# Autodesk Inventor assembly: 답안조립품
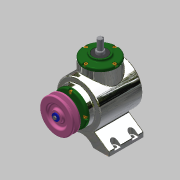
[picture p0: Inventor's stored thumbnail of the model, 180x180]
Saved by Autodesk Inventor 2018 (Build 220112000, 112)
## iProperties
Created: 2021-04
Part Number: 답안조립품
Material: 일반
Document SubType Name: Assembly
Designer: home
Author: home
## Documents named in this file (17)
- C:\Users\home\Desktop\710407V1014\답안조립품.iam
- C:\Users\home\Desktop\710407V1014\본체.ipt
- C:\Users\home\Desktop\710407V1014\커버.ipt
- C:\Users\home\Desktop\710407V1014\베어링 6203.ipt
- C:\Users\home\Desktop\710407V1014\오일실 17 x 32 x 8.ipt
- C:\Users\home\Desktop\710407V1014\메인 축.ipt
- 메인 축.ipt
- C:\Users\home\Desktop\710407V1014\키 5 x 5 x 14.ipt
- C:\Users\home\Desktop\710407V1014\메인 베벨기어.ipt
- C:\Users\home\Desktop\710407V1014\서브 축.ipt
- 서브 축.ipt
- C:\Users\home\Desktop\710407V1014\키 4 x 4 x 14.ipt
- C:\Users\home\Desktop\710407V1014\서브 베벨기어.ipt
- C:\Users\home\Desktop\710407V1014\V-벨트풀리.ipt
- C:\Users\home\Desktop\710407V1014\볼트 M4 x 10.ipt
- C:\Users\home\Desktop\710407V1014\와셔 4 x 16.ipt
- C:\Users\home\Desktop\710407V1014\육각볼트 M4 x 8.ipt
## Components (1 placed, 1 different names)
1. V-벨트풀리:1 — 각도:4
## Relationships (1: Angle 1)
- 각도:4 [Angle]: V-벨트풀리:1
